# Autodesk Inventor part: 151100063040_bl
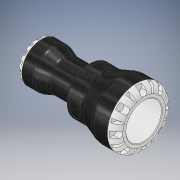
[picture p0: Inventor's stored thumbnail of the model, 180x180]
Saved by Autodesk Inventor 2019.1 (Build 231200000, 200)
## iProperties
Created: 2016-12
Part Number: 151100063040_bl
Material: PVC-Piping
Description: PLASSON G-PLASS  REDUCING COUPLING  63 x 40
Document SubType Name: Modeling
Designer: KIM
Mass: 309.689 g
Surface Area: 488.063 cm^2
Volume: 221.206 cm^3
Density: 1.4 g/cm^3
Appearance: Black Cast
Author: KIM
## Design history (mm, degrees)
derived "151100.ipt"
feature "Solid1::151100.ipt" dims "ScaleForDerivedMember" = 10
tag "TaggingFeature1"
body "Solid1"
other parameters: "d_" = 63 [user parameter], "E_" = 103 [user parameter], "H_" = 192 [user parameter], "l_" = 96 [user parameter], "l1" = 75 [user parameter], "Plasson" = 1 [user parameter], "d21" = 13.7 [user parameter], "d23" = 103 [user parameter], "d24" = 75.6 [user parameter], "d59" = 22.93938 [user parameter], "d0" = 192 [user parameter], "d2" = 40.32 [user parameter], "d3" = 63 [user parameter], "d4" = 103 [user parameter], "d5" = 75.6 [user parameter], "d6" = 96 [user parameter], "d7" = 5.25 [user parameter], "d11" = 31.5 [user parameter], "d12" = 75 [user parameter], "d13" = 3.33333 [user parameter], "d14" = 82.4 [user parameter], "d15" = 56 [user parameter], "d16" = 20 deg [user parameter], "d17" = 20 deg [user parameter], "d18" = 130 deg [user parameter], "d22" = 10.96 [user parameter], "d25" = 10.96 [user parameter], "d26" = 0 [user parameter], "d28" = 360 deg [user parameter], "d30" = 8 deg [user parameter], "d31" = 1.26 [user parameter], "d32" = 8 deg [user parameter], "d33" = 1.26 [user parameter], "d35" = 0 [user parameter], "d37" = 360 deg [user parameter], "d39" = 8 [user parameter], "d42" = 8 [user parameter], "d43" = 0 [user parameter], "d45" = 360 deg [user parameter], "d47" = 0.8 [user parameter], "d48" = 8 deg [user parameter], "d49" = 8 deg [user parameter], "d50" = 0.8 [user parameter], "d52" = 0 [user parameter], "d54" = 360 deg [user parameter], "d56" = 14 [user parameter], "d57" = 20.6 [user parameter], "d58" = 0.5 [user parameter], "d60" = 12.36 [user parameter], "d61" = 15.75 [user parameter], "d62" = 17.46 [user parameter], "d63" = 0 [user parameter], "d66" = 0 [user parameter], "d68" = 360 deg [user parameter], "d75" = 11.46969 [user parameter], "d77" = 80.34 [user parameter], "d78" = 1.03 [user parameter]
